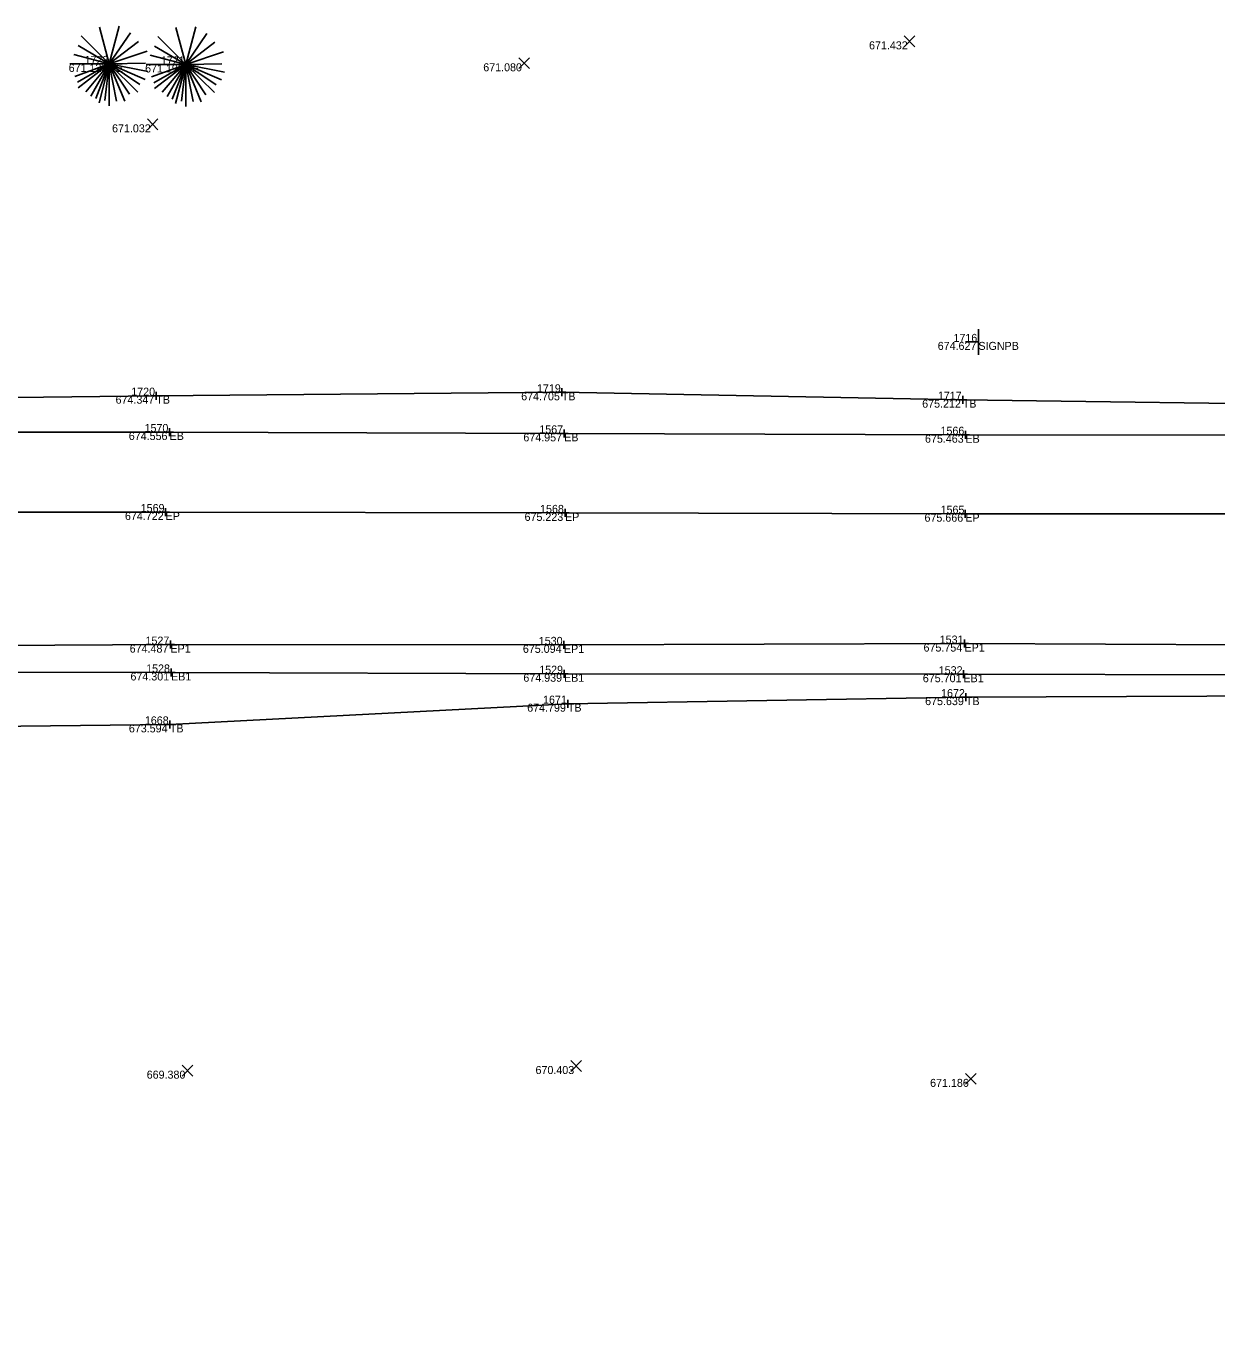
# Model space of a CAD drawing. Extents: x 2197382 to 2204062, y 634117 to 636522.
# Drawn here: x 2203541.7 to 2203690.4, y 635419.8 to 635584.3 of the extents above; entities that cross this region are included whole.
import ezdxf

# ---------------------------------------------------------------- set-up
doc = ezdxf.new("R2010")
doc.units = 0
for name, color, linetype in [('_CIVIL_CONSTRUCTION', 7, 'Continuous'), ('GE_P_Alignment_100_Bearings', 7, 'Continuous'), ('GE_P_Alignment_100_Distances', 7, 'Continuous'), ('GE_P_Alignment_100_Stations', 7, 'Continuous'), ('GE_X_Alignment', 7, 'Continuous'), ('PF_P_Grade_Line', 7, 'Continuous'), ('RW_X_CL_100_Curve_Data', 7, 'Continuous'), ('SH_Border', 7, 'Continuous'), ('SH_Cut_Line', 7, 'Continuous'), ('SH_Data', 7, 'Continuous')]:
    doc.layers.add(name, color=color, linetype=linetype)

msp = doc.modelspace()

# ---------------------------------------------------------------- linework, layer by layer
at = {"layer": '_CIVIL_CONSTRUCTION'}
for p, q in [((2203608.57, 635539.11), (2203608.57, 635538.11)), ((2203557.41, 635538.19), (2203558.41, 635538.19)), ((2203557.91, 635538.69), (2203557.91, 635537.69)), ((2203557.91, 635538.19), (2203557.91, 635538.19)), ((2203608.07, 635538.61), (2203609.07, 635538.61)), ((2203608.57, 635538.61), (2203608.57, 635538.61)), ((2203658.17, 635537.69), (2203659.17, 635537.69)), ((2203658.67, 635538.19), (2203658.67, 635537.19)), ((2203658.67, 635537.69), (2203658.67, 635537.69)), ((2203559.57, 635534.15), (2203559.57, 635533.15)), ((2203608.87, 635533.98), (2203608.87, 635532.98)), ((2203559.07, 635533.65), (2203560.07, 635533.65)), ((2203559.57, 635533.65), (2203559.57, 635533.65)), ((2203608.37, 635533.48), (2203609.37, 635533.48)), ((2203608.87, 635533.48), (2203608.87, 635533.48)), ((2203658.51, 635533.31), (2203659.51, 635533.31)), ((2203659.01, 635533.81), (2203659.01, 635532.81)), ((2203659.01, 635533.31), (2203659.01, 635533.31)), ((2203559.07, 635524.15), (2203559.07, 635523.15)), ((2203558.57, 635523.65), (2203559.57, 635523.65)), ((2203559.07, 635523.65), (2203559.07, 635523.65)), ((2203608.48, 635523.54), (2203609.48, 635523.54)), ((2203608.98, 635524.04), (2203608.98, 635523.04)), ((2203608.98, 635523.54), (2203608.98, 635523.54)), ((2203658.49, 635523.44), (2203659.49, 635523.44)), ((2203658.99, 635523.94), (2203658.99, 635522.94)), ((2203658.99, 635523.44), (2203658.99, 635523.44)), ((2203658.89, 635507.71), (2203658.89, 635506.71)), ((2203559.18, 635507.08), (2203560.18, 635507.08)), ((2203559.68, 635507.58), (2203559.68, 635506.58)), ((2203559.68, 635507.08), (2203559.68, 635507.08)), ((2203608.34, 635507.05), (2203609.34, 635507.05)), ((2203608.84, 635507.55), (2203608.84, 635506.55)), ((2203608.84, 635507.05), (2203608.84, 635507.05)), ((2203658.39, 635507.21), (2203659.39, 635507.21)), ((2203658.89, 635507.21), (2203658.89, 635507.21)), ((2203559.26, 635503.6), (2203560.26, 635503.6)), ((2203559.76, 635504.1), (2203559.76, 635503.1)), ((2203559.76, 635503.6), (2203559.76, 635503.6)), ((2203608.35, 635503.44), (2203609.35, 635503.44)), ((2203608.85, 635503.94), (2203608.85, 635502.94)), ((2203608.85, 635503.44), (2203608.85, 635503.44)), ((2203658.26, 635503.38), (2203659.26, 635503.38)), ((2203658.76, 635503.88), (2203658.76, 635502.88)), ((2203658.76, 635503.38), (2203658.76, 635503.38)), ((2203608.83, 635499.7), (2203609.83, 635499.7)), ((2203609.33, 635500.2), (2203609.33, 635499.2)), ((2203609.33, 635499.7), (2203609.33, 635499.7)), ((2203658.56, 635500.52), (2203659.56, 635500.52)), ((2203659.06, 635501.02), (2203659.06, 635500.02)), ((2203659.06, 635500.52), (2203659.06, 635500.52)), ((2203559.1, 635497.11), (2203560.1, 635497.11)), ((2203559.6, 635497.61), (2203559.6, 635496.61)), ((2203559.6, 635497.11), (2203559.6, 635497.11))]:
    msp.add_line(p, q, dxfattribs=at)
at = {"layer": 'GE_P_Alignment_100_Bearings'}
for p, q in [((2203552.03, 635579.65), (2203550.8, 635584.26)), ((2203552.03, 635579.65), (2203553.29, 635584.35)), ((2203552.03, 635579.65), (2203554.69, 635583.53)), ((2203561.58, 635579.58), (2203560.34, 635584.19)), ((2203561.58, 635579.58), (2203562.83, 635584.28)), ((2203561.58, 635579.58), (2203564.23, 635583.46)), ((2203552.03, 635579.65), (2203548.13, 635581.95)), ((2203552.03, 635579.65), (2203548.54, 635583.14)), ((2203552.03, 635579.65), (2203555.69, 635582.45)), ((2203561.58, 635579.58), (2203557.67, 635581.87)), ((2203561.58, 635579.58), (2203558.09, 635583.06)), ((2203561.58, 635579.58), (2203565.23, 635582.38)), ((2203552.03, 635579.65), (2203547.62, 635580.83)), ((2203552.03, 635579.65), (2203556.77, 635581.26)), ((2203561.58, 635579.58), (2203557.16, 635580.76)), ((2203561.58, 635579.58), (2203566.31, 635581.18)), ((2203547.1, 635579.65), (2203552.03, 635579.65)), ((2203552.03, 635579.65), (2203547.74, 635578.09)), ((2203552.03, 635579.65), (2203548.05, 635577.37)), ((2203552.03, 635579.65), (2203548.13, 635576.65)), ((2203552.03, 635579.65), (2203549.09, 635576.18)), ((2203552.03, 635579.65), (2203549.71, 635575.63)), ((2203552.03, 635579.65), (2203550.37, 635575.31)), ((2203552.03, 635579.65), (2203550.77, 635574.79)), ((2203552.03, 635579.65), (2203551.49, 635575.06)), ((2203552.03, 635579.65), (2203556.54, 635579.74)), ((2203552.03, 635574.41), (2203552.03, 635579.65)), ((2203552.03, 635579.65), (2203552.95, 635575.01)), ((2203552.03, 635579.65), (2203553.97, 635574.98)), ((2203552.03, 635579.65), (2203554.57, 635575.86)), ((2203552.03, 635579.65), (2203555.62, 635576.13)), ((2203552.03, 635579.65), (2203555.85, 635577.09)), ((2203552.03, 635579.65), (2203556.5, 635577.71)), ((2203552.03, 635579.65), (2203556.86, 635578.69)), ((2203556.64, 635579.58), (2203561.58, 635579.58)), ((2203561.58, 635579.58), (2203557.29, 635578.02)), ((2203561.58, 635579.58), (2203557.59, 635577.3)), ((2203561.58, 635579.58), (2203557.67, 635576.58)), ((2203561.58, 635579.58), (2203558.63, 635576.11)), ((2203561.58, 635579.58), (2203559.26, 635575.56)), ((2203561.58, 635579.58), (2203559.91, 635575.24)), ((2203561.58, 635579.58), (2203560.31, 635574.72)), ((2203561.58, 635579.58), (2203561.04, 635574.99)), ((2203561.58, 635579.58), (2203566.09, 635579.67)), ((2203561.58, 635574.34), (2203561.58, 635579.58)), ((2203561.58, 635579.58), (2203562.5, 635574.94)), ((2203561.58, 635579.58), (2203563.51, 635574.91)), ((2203561.58, 635579.58), (2203564.11, 635575.78)), ((2203561.58, 635579.58), (2203565.17, 635576.06)), ((2203561.58, 635579.58), (2203565.4, 635577.02)), ((2203561.58, 635579.58), (2203566.04, 635577.64)), ((2203561.58, 635579.58), (2203566.41, 635578.62))]:
    msp.add_line(p, q, dxfattribs=at)
at = {"layer": 'GE_P_Alignment_100_Distances'}
for p, q in [((2203559.07, 635523.65), (2203509.32, 635523.64)), ((2203608.98, 635523.54), (2203559.07, 635523.65)), ((2203658.99, 635523.44), (2203608.98, 635523.54)), ((2203708.82, 635523.4), (2203658.99, 635523.44)), ((2203509.37, 635506.86), (2203559.68, 635507.08)), ((2203559.68, 635507.08), (2203608.84, 635507.05)), ((2203608.84, 635507.05), (2203658.89, 635507.21)), ((2203658.89, 635507.21), (2203708.55, 635506.97))]:
    msp.add_line(p, q, dxfattribs=at)
at = {"layer": 'GE_P_Alignment_100_Stations'}
for p, q in [((2203660.63, 635546.51), (2203660.63, 635543.31)), ((2203660.63, 635544.91), (2203659.03, 635544.91))]:
    msp.add_line(p, q, dxfattribs=at)
at = {"layer": 'GE_X_Alignment'}
for p, q in [((2203559.57, 635533.65), (2203509.05, 635533.64)), ((2203608.87, 635533.48), (2203559.57, 635533.65)), ((2203659.01, 635533.31), (2203608.87, 635533.48)), ((2203709.06, 635533.22), (2203659.01, 635533.31)), ((2203508.72, 635503.64), (2203559.76, 635503.6)), ((2203559.76, 635503.6), (2203608.85, 635503.44)), ((2203608.85, 635503.44), (2203658.76, 635503.38)), ((2203658.76, 635503.38), (2203708.25, 635503.3))]:
    msp.add_line(p, q, dxfattribs=at)
at = {"layer": 'PF_P_Grade_Line'}
for points in [[(2203905.24, 635544.12), (2203857.35, 635543.05), (2203808.12, 635540.24), (2203758.65, 635537.75), (2203707.87, 635536.99), (2203658.67, 635537.69), (2203608.57, 635538.61), (2203557.91, 635538.19), (2203508.63, 635537.6), (2203457.14, 635535.79), (2203407.8, 635532.16), (2203358.09, 635527.85), (2203307.62, 635521.36), (2203257.61, 635512.38), (2203209.52, 635502.64), (2203160.69, 635490.38), (2203110.74, 635480.72), (2203062.69, 635468.06), (2203015.53, 635449.98), (2202971.3, 635427.61)], [(2203043.47, 635419.84), (2203073.57, 635429.53), (2203121.13, 635443.22), (2203169.12, 635455.8), (2203217.36, 635467.56), (2203230.84, 635471.04), (2203265.33, 635478.99), (2203314.75, 635483.37), (2203364.47, 635491.57), (2203411.45, 635493.02), (2203461.51, 635493.07), (2203507.42, 635496.53), (2203559.6, 635497.11), (2203609.33, 635499.7), (2203659.06, 635500.52), (2203709.25, 635500.73), (2203757.56, 635500.46), (2203810.24, 635498.93), (2203858.69, 635500.09), (2203907.88, 635499.67), (2203958.73, 635497.99), (2204007.22, 635491.87), (2204054.41, 635491.83)]]:
    msp.add_lwpolyline(points, dxfattribs=at)
at = {"layer": 'RW_X_CL_100_Curve_Data'}
for p, q in [((2203651.37, 635581.8), (2203652.7, 635583.14)), ((2203651.37, 635583.14), (2203652.7, 635581.8)), ((2203603.21, 635579.06), (2203604.54, 635580.4)), ((2203603.21, 635580.4), (2203604.54, 635579.06)), ((2203556.79, 635571.43), (2203558.12, 635572.77)), ((2203556.79, 635572.77), (2203558.12, 635571.43)), ((2203609.69, 635453.75), (2203611.02, 635455.09)), ((2203609.69, 635455.09), (2203611.02, 635453.75)), ((2203561.16, 635453.17), (2203562.49, 635454.51)), ((2203561.16, 635454.51), (2203562.49, 635453.17)), ((2203659.03, 635452.14), (2203660.36, 635453.48)), ((2203659.03, 635453.48), (2203660.36, 635452.14))]:
    msp.add_line(p, q, dxfattribs=at)

# ---------------------------------------------------------------- texts
at = {"layer": 'SH_Border'}
for s, p in [('TE', (2203552.03, 635578.65)), ('TE', (2203561.58, 635578.58)), ('SIGNPB', (2203660.63, 635543.91)), ('TB', (2203557.91, 635537.19)), ('TB', (2203608.57, 635537.61)), ('TB', (2203658.67, 635536.69)), ('EB', (2203559.57, 635532.65)), ('EB', (2203608.87, 635532.48)), ('EB', (2203659.01, 635532.31)), ('EP', (2203559.07, 635522.65)), ('EP', (2203608.98, 635522.54)), ('EP', (2203658.99, 635522.44)), ('EP1', (2203559.68, 635506.08)), ('EP1', (2203608.84, 635506.05)), ('EP1', (2203658.89, 635506.21)), ('EB1', (2203559.76, 635502.6)), ('EB1', (2203608.85, 635502.44)), ('EB1', (2203658.76, 635502.38)), ('TB', (2203609.33, 635498.7)), ('TB', (2203659.06, 635499.52)), ('TB', (2203559.6, 635496.11))]:
    msp.add_text(s, height=1, dxfattribs=at).set_placement(p)
at = {"layer": 'SH_Cut_Line'}
for s, p in [('1723', (2203548.95, 635579.65)), ('1721', (2203558.48, 635579.58)), ('1716', (2203657.51, 635544.91)), ('1720', (2203554.78, 635538.19)), ('1719', (2203605.47, 635538.61)), ('1717', (2203655.56, 635537.69)), ('1570', (2203556.44, 635533.65)), ('1567', (2203605.76, 635533.48)), ('1566', (2203655.89, 635533.31)), ('1569', (2203555.96, 635523.65)), ('1568', (2203605.86, 635523.54)), ('1565', (2203655.9, 635523.44)), ('1527', (2203556.56, 635507.08)), ('1530', (2203605.7, 635507.05)), ('1531', (2203655.79, 635507.21)), ('1528', (2203556.64, 635503.6)), ('1529', (2203605.75, 635503.44)), ('1532', (2203655.67, 635503.38)), ('1672', (2203655.96, 635500.52)), ('1671', (2203606.23, 635499.7)), ('1668', (2203556.48, 635497.11))]:
    msp.add_text(s, height=1, dxfattribs=at).set_placement(p)
at = {"layer": 'SH_Data'}
for s, p in [('671.432', (2203646.96, 635581.47)), ('671.125', (2203546.96, 635578.65)), ('671.195', (2203556.51, 635578.58)), ('671.080', (2203598.76, 635578.73)), ('671.032', (2203552.38, 635571.1)), ('674.627', (2203655.54, 635543.91)), ('674.347', (2203552.82, 635537.19)), ('674.705', (2203603.5, 635537.61)), ('675.212', (2203653.6, 635536.69)), ('674.556', (2203554.47, 635532.65)), ('674.957', (2203603.77, 635532.48)), ('675.463', (2203653.95, 635532.31)), ('674.722', (2203553.99, 635522.65)), ('675.223', (2203603.92, 635522.54)), ('675.666', (2203653.89, 635522.44)), ('674.487', (2203554.58, 635506.08)), ('675.094', (2203603.71, 635506.05)), ('675.754', (2203653.77, 635506.21)), ('674.301', (2203554.68, 635502.6)), ('674.939', (2203603.77, 635502.44)), ('675.701', (2203653.68, 635502.38)), ('674.799', (2203604.25, 635498.7)), ('675.639', (2203653.97, 635499.52)), ('673.594', (2203554.48, 635496.11)), ('669.380', (2203556.71, 635452.84)), ('670.403', (2203605.29, 635453.42)), ('671.186', (2203654.59, 635451.81))]:
    msp.add_text(s, height=1, dxfattribs=at).set_placement(p)

doc.saveas('drawing.dxf')
